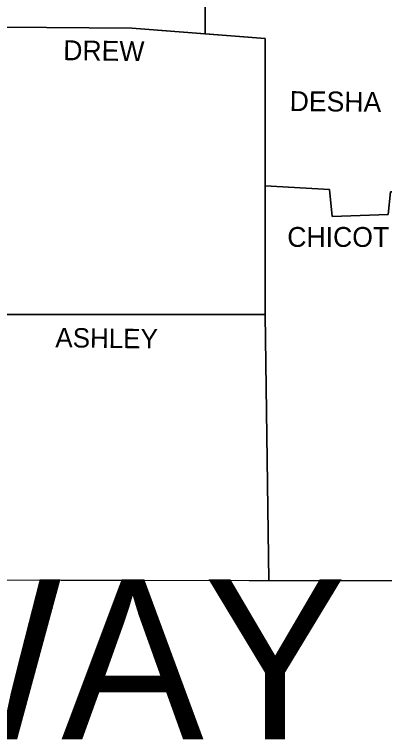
# Model space of a CAD drawing. Extents: x -28335 to 1228743, y -22428 to 152440.
# Drawn here: x 32020 to 33833, y 4514 to 8075 of the extents above; entities that cross this region are included whole.
import ezdxf

# ---------------------------------------------------------------- set-up
doc = ezdxf.new("R2010")
doc.units = 0
doc.layers.add('16', color=7, linetype='Continuous')
doc.layers.add('8', color=7, linetype='Continuous')

msp = doc.modelspace()

# ---------------------------------------------------------------- linework, layer by layer
at = {"layer": '16'}
for p, q in [((32955.7, 8658.5), (32953.5, 7981.1)), ((32953.5, 7981.1), (33248, 7958.5)), ((33248, 7958.5), (33248, 7236.6)), ((33248, 7236.6), (33248, 6606.1)), ((33248, 7236.6), (33562.8, 7217.8)), ((33562.8, 7217.8), (33576.4, 7086.4)), ((33576.4, 7086.4), (33850.5, 7095.4)), ((31760.8, 6606.1), (33248, 6606.1)), ((33248, 6606.1), (31760.8, 6606.1)), ((31479.5, 5305.6), (33266.1, 5302.7)), ((33266.1, 5302.7), (34092.9, 5301.4))]:
    msp.add_line(p, q, dxfattribs=at)
for points in [[(32953.5, 7981.1), (32955.7, 8658.5), (33170.9, 8658.5), (33177.7, 8740), (33297.8, 8751.3), (33325, 8812.5)], [(31757.5, 8015.1), (32595.5, 8008.3), (32953.5, 7981)], [(33248, 7958.5), (32953.5, 7981), (32595.5, 8008.3), (31757.5, 8015.1)], [(32953.5, 7981), (32953.5, 7981.1)], [(33248, 6606.1), (33248, 7236.6), (33248, 7958.5)], [(33946.6, 7206.4), (33861.9, 7206.4), (33850.5, 7095.4), (33576.4, 7086.4), (33562.8, 7217.8), (33248, 7236.6)], [(33266.1, 5302.7), (33248, 6603.9), (33248, 6606.1)], [(33248, 6606.1), (33248, 6603.9), (33266.1, 5302.7)]]:
    msp.add_lwpolyline(points, dxfattribs=at)
at = {"layer": '8'}
for points in [[(33325, 8812.5), (33297.8, 8751.3), (33177.7, 8740), (33170.9, 8658.5), (32955.7, 8658.5), (32953.5, 7981.1)], [(31755.1, 8015.1), (32595.5, 8008.3), (33248, 7958.5)], [(33248, 7958.5), (33248, 6603.9), (33266.1, 5302.7)], [(33248, 7236.6), (33562.8, 7217.8), (33576.4, 7086.4), (33850.5, 7095.4), (33861.9, 7206.4), (33946.6, 7206.4)], [(25786.1, 7147.5), (25790.6, 5314.9), (34092.9, 5301.4)], [(31760.8, 6606.1), (33248, 6606.1)]]:
    msp.add_lwpolyline(points, dxfattribs=at)

# ---------------------------------------------------------------- texts
for s, height, rotation, p in [('DREW', 97.39, 359.2258, (32258, 7852)), ('DESHA', 97.39, 359.3704, (33368, 7602.8)), ('ASHLEY', 95.15, 359.2361, (32219.5, 6445.3))]:
    msp.add_text(s, height=height, rotation=rotation, dxfattribs=at).set_placement(p)
for s, height, p in [('CHICOT', 97.41, (33356.7, 6936.9)), ('ARKANSAS HIGHWAY DISTRICT 10', 783.393, (22644.5, 4524.8))]:
    msp.add_text(s, height=height, dxfattribs=at).set_placement(p)

doc.saveas('drawing.dxf')
